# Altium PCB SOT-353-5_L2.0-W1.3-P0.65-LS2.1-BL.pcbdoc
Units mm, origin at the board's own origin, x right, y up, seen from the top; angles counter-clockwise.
Board outline 15.15 x 15.28 mm, 2 copper layers (Top Layer, Bottom Layer), stack 0 mm thick; 1 components, 0 nets, 5 pads, 0 vias.
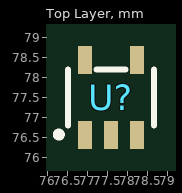
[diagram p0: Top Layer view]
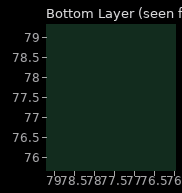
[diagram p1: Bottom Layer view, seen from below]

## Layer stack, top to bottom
Top Layer: signal copper (thickness not stored)
Bottom Layer: signal copper (thickness not stored)

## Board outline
85.004,69.85 69.85,69.85 69.85,85.13 85.004,85.13

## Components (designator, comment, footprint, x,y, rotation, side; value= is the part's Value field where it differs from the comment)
U? "" SOT-353-5_L2.0-W1.3-P0.65-LS2.1-BL 77.577,77.49 r0 top

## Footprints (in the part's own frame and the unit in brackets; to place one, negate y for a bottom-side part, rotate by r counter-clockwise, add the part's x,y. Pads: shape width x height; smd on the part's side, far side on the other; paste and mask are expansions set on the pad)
SOT-353-5_L2.0-W1.3-P0.65-LS2.1-BL [mm]
  rect 0.35x0.7 smd: 1(-0.65,-0.94) 2(0,-0.94) 3(0.65,-0.94) 4(0.65,0.94) 5(-0.65,0.94)
  silkscreen extent -1.38,-1 1.08,0.7

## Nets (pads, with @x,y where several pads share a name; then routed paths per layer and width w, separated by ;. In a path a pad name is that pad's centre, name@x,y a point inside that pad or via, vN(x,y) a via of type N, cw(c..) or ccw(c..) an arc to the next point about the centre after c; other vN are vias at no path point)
pads on no net: U?.1 U?.2 U?.3 U?.4 U?.5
